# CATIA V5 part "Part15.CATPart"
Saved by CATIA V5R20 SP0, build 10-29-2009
Part number: 9AE031620-3
Revision: ANY
Definition: UNKNOWN
Nomenclature: 9AE031620-3
Source: Unknown
Bounding box of the stored display mesh (mm): x -6.55 to 12.95, y -19 to 27, z -9.75 to 9.75
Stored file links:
  C:\Users\Utente\Desktop\IO LAVORO\3D X SITO CF\CUMSA\3D files AE\AE 041620\Part15.CATPart
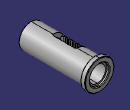
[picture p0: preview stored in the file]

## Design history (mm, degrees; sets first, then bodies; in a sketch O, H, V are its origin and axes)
Body1 "Cortar-Barrer1" (main body)
  Solid1: solid without history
